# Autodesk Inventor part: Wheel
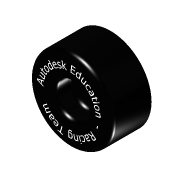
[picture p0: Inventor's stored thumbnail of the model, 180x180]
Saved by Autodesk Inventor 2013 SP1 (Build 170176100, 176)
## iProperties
Created: 2013-01
Part Number: Wheel
Material: ABS Plastic
Document SubType Name: Modeling
Designer: banachd
Density: 1 g/cm^3
Description: 30 mm DIA x 15 mm WHEEL
Author: banachd
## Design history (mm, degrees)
sketch "Sketch1"
  geometry: L1 (0, 0)-(0, -7); L2 (0, -7)-(6, -7); L3 (6, -7)-(6, -14.75); L4 (15, -14.75)-(15, 0); L5 (15, 0)-(0, 0); L6 (6, -14.75)-(15, -14.75); A1 r 40.625 centre (10.5, 25.625) between (6, -14.75) and (15, -14.75)
  constraints: 12 end point, 4 parallel, 3 point on circle, 1 centre point, 1 horizontal alignment, 1 perpendicular, 1 vertical
  dimensions: "d2" = 30 diameter of L4 L1; "d4" = 12 diameter of L3 L1; "d5" = 15 distance edge to line of A1 L5; "d6" = 0.25 distance edge to line of A1 L6; "d7" = 7 distance of L1.start L1.end
revolve "Revolution1" sketch "Sketch1" stored, may be unused: angle "d8" = 90 deg
hole "Hole1" diameter "d11" = 3; stored, may be unused: countersink angle "d15" = 90 deg, drill point angle "d17" = 118 deg; dims "d9" = 10, "d10" = 10, "d12" = 6, "d13" = 4, "d14" = 2, "d16" = 8
fillet "Fillet1" dims "d18" = 2
workplane "Work Plane1"
shell "Shell1" dims "d19" = 1
sketch "Sketch2"
  geometry: C1 r 9.5 at (0, 0); 1 further point
  constraints: 1 centre point, 1 coincident, 1 other
  dimensions: "d21" = 19 diameter of C1
emboss "Emboss1" sketch "Sketch2" dims "d2" = 30, "d23" = 0.1, "d24" = 0
body "Solid1"
other parameters: "d20" = -15
